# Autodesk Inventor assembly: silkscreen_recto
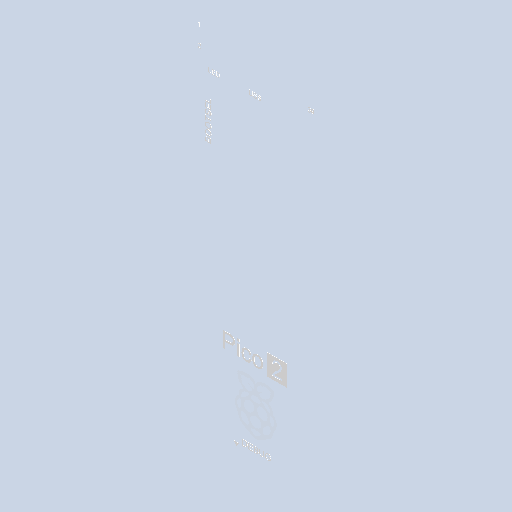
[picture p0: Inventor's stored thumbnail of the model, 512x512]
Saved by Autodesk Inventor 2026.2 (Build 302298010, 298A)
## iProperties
Created: 2026-10
Part Number: silkscreen_recto
Document SubType Name: Assembly
Designer: mel
Author: mel
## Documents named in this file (12)
- D:\travail\année 2026-2027\1 sti2d IT\poubelle à verre\raspberry-pico-2-microcontroller-rp2350-1.snapshot.5\raspberry_pico_2\raspberry_pico_2\silkscreen_recto.iam
- D:\travail\année 2026-2027\1 sti2d IT\poubelle à verre\raspberry-pico-2-microcontroller-rp2350-1.snapshot.5\raspberry_pico_2\raspberry_pico_2\Text_debug.ipt
- D:\travail\année 2026-2027\1 sti2d IT\poubelle à verre\raspberry-pico-2-microcontroller-rp2350-1.snapshot.5\raspberry_pico_2\raspberry_pico_2\fleche_debug.ipt
- D:\travail\année 2026-2027\1 sti2d IT\poubelle à verre\raspberry-pico-2-microcontroller-rp2350-1.snapshot.5\raspberry_pico_2\raspberry_pico_2\text_Pico.ipt
- D:\travail\année 2026-2027\1 sti2d IT\poubelle à verre\raspberry-pico-2-microcontroller-rp2350-1.snapshot.5\raspberry_pico_2\raspberry_pico_2\2_on_white.ipt
- D:\travail\année 2026-2027\1 sti2d IT\poubelle à verre\raspberry-pico-2-microcontroller-rp2350-1.snapshot.5\raspberry_pico_2\raspberry_pico_2\Text_led.ipt
- D:\travail\année 2026-2027\1 sti2d IT\poubelle à verre\raspberry-pico-2-microcontroller-rp2350-1.snapshot.5\raspberry_pico_2\raspberry_pico_2\Text_usb.ipt
- D:\travail\année 2026-2027\1 sti2d IT\poubelle à verre\raspberry-pico-2-microcontroller-rp2350-1.snapshot.5\raspberry_pico_2\raspberry_pico_2\Text_BOOTSEL.ipt
- D:\travail\année 2026-2027\1 sti2d IT\poubelle à verre\raspberry-pico-2-microcontroller-rp2350-1.snapshot.5\raspberry_pico_2\raspberry_pico_2\Text_1.ipt
- D:\travail\année 2026-2027\1 sti2d IT\poubelle à verre\raspberry-pico-2-microcontroller-rp2350-1.snapshot.5\raspberry_pico_2\raspberry_pico_2\Text_l2.ipt
- D:\travail\année 2026-2027\1 sti2d IT\poubelle à verre\raspberry-pico-2-microcontroller-rp2350-1.snapshot.5\raspberry_pico_2\raspberry_pico_2\Text_39.ipt
- D:\travail\année 2026-2027\1 sti2d IT\poubelle à verre\raspberry-pico-2-microcontroller-rp2350-1.snapshot.5\raspberry_pico_2\raspberry_pico_2\Scale003.ipt
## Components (11 placed, 11 different names)
1. 2652
2. 2653
3. 2654
4. 2655
5. 2656
6. 2657
7. 2658
8. 2659
9. 2660
10. 2661
11. 2662
